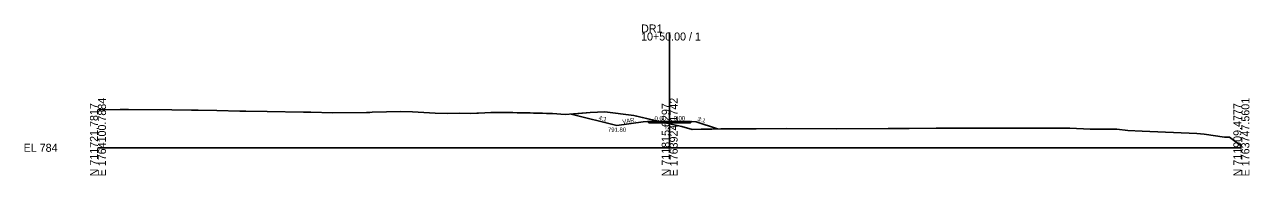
# Model space of a CAD drawing. Extents: x -26 to 403, y -10 to 2023.
# Drawn here: x -25.7 to 402.8, y 990.3 to 1043.1 of the extents above; entities that cross this region are included whole.
import ezdxf

# ---------------------------------------------------------------- set-up
doc = ezdxf.new("R2010")
doc.units = 0
for name, color, linetype in [('Exist Cross Section Cell', 7, 'Continuous'), ('Exist XS Center Line Elevation Label', 7, 'Continuous'), ('Exist XS Ground Line', 7, 'Continuous'), ('Prop CMT Pvmt Surface', 7, 'Continuous'), ('Prop CMT Slope Grass', 7, 'Continuous'), ('Prop CMT Subgrade Earthwork', 7, 'Continuous'), ('Prop XS Earthwork Shape', 7, 'Continuous'), ('Prop XS Side Slope Text', 7, 'Continuous')]:
    doc.layers.add(name, color=color, linetype=linetype)

msp = doc.modelspace()

# ---------------------------------------------------------------- linework, layer by layer
at = {"layer": 'Exist Cross Section Cell'}
for p, q in [((200, 1000), (200, 1040.33)), ((0, 1000), (200, 1000)), ((200, 1000), (400, 1000))]:
    msp.add_line(p, q, dxfattribs=at)
at = {"layer": 'Exist XS Ground Line'}
msp.add_lwpolyline([(0, 1013.23), (7.79, 1013.44), (10.66, 1013.44), (25.89, 1013.29), (32.72, 1013.19), (35.04, 1013.13), (41.56, 1013.02), (49.63, 1012.85), (50.72, 1012.83), (51.02, 1012.8), (51.76, 1012.77), (59.14, 1012.67), (71.87, 1012.47), (74.49, 1012.43), (82.06, 1012.26), (93.89, 1012.39), (95.12, 1012.38), (95.94, 1012.41), (105.9, 1012.74), (110.01, 1012.62), (117.91, 1012.17), (122.14, 1012.01), (126.56, 1012.06), (130.5, 1011.94), (132.54, 1012.13), (133.07, 1012.15), (135.37, 1012.23), (137.39, 1012.33), (138.2, 1012.37), (139.12, 1012.36), (141.03, 1012.34), (142.72, 1012.34), (143.86, 1012.34), (145.16, 1012.3), (146.69, 1012.27), (148.04, 1012.24), (149.52, 1012.23), (151.2, 1012.18), (152.35, 1012.16), (153.37, 1012.14), (155.47, 1012.09), (156.9, 1012), (158.97, 1011.94), (163.41, 1011.63), (172.23, 1012.34), (177.29, 1012.58), (187.46, 1011.25), (200, 1008.41), (204.22, 1007.45), (207.83, 1006.38), (211.02, 1006.49), (214.77, 1006.56), (217.85, 1006.6), (219.41, 1006.59), (221.85, 1006.59), (224.18, 1006.6), (230.21, 1006.68), (241, 1006.72), (258.52, 1006.65), (276.42, 1006.78), (283.8, 1006.8), (293.23, 1006.83), (322.06, 1006.9), (323.31, 1006.9), (328.03, 1006.91), (328.64, 1006.91), (336.97, 1006.9), (339.98, 1006.9), (347.14, 1006.54), (356.43, 1006.55), (360.28, 1006.05), (365.29, 1005.78), (384.37, 1005.04), (386.95, 1004.76), (394.15, 1003.75), (395.87, 1003.68), (398.22, 1001.98), (400, 1000.54)], dxfattribs=at)
at = {"layer": 'Prop CMT Pvmt Surface'}
for p, q in [((200, 1009.25), (192.73, 1009.25)), ((207.27, 1009.25), (200, 1009.25))]:
    msp.add_line(p, q, dxfattribs=at)
at = {"layer": 'Prop CMT Slope Grass'}
for p, q in [((181.52, 1007.8), (165.51, 1011.8)), ((181.52, 1007.8), (190.73, 1009.09)), ((209.27, 1009.09), (216.77, 1006.58))]:
    msp.add_line(p, q, dxfattribs=at)
for points in [[(192.73, 1009.25), (190.73, 1009.09)], [(207.27, 1009.25), (209.27, 1009.09)]]:
    msp.add_lwpolyline(points, dxfattribs=at)
at = {"layer": 'Prop CMT Subgrade Earthwork'}
for p, q in [((192.73, 1008.75), (192.27, 1009.21)), ((200, 1008.75), (192.73, 1008.75)), ((207.27, 1008.75), (200, 1008.75)), ((207.27, 1008.75), (207.73, 1009.21))]:
    msp.add_line(p, q, dxfattribs=at)
at = {"layer": 'Prop XS Earthwork Shape'}
for points in [[(181.52, 1007.8), (190.73, 1009.09), (192.27, 1009.21), (192.73, 1009.25), (196.29, 1009.25), (187.46, 1011.25), (177.29, 1012.58), (172.23, 1012.34), (165.51, 1011.8)], [(198.5, 1008.75), (192.73, 1008.75), (192.27, 1009.21), (192.73, 1009.25), (196.29, 1009.25)], [(207.27, 1008.75), (207.73, 1009.21), (209.27, 1009.09), (216.77, 1006.58), (214.77, 1006.56), (211.02, 1006.49), (207.83, 1006.38), (204.22, 1007.45), (200, 1008.41), (198.5, 1008.75), (200, 1008.75)]]:
    msp.add_lwpolyline(points, close=True, dxfattribs=at)

# ---------------------------------------------------------------- texts
at = {"layer": 'Exist Cross Section Cell'}
for s, p in [('DR1', (190, 1040.33)), ('10+50.00 / 1', (190, 1037.53)), ('EL 784', (-26, 998.6))]:
    msp.add_text(s, height=2.8, dxfattribs=at).set_placement(p)
for s, p in [('E 1764100.7884', (2.8, 990)), ('E 1763924.1742', (202.8, 990)), ('E 1763747.5601', (402.8, 990)), ('N 711721.7817', (0, 990)), ('N 711815.6297', (200, 990)), ('N 711909.4777', (400, 990))]:
    msp.add_text(s, height=2.8, rotation=90, dxfattribs=at).set_placement(p)
at = {"layer": 'Exist XS Center Line Elevation Label'}
for s, height, p in [('791.80', 1.5, (178.42, 1005.59)), ('792.41', 1, (198.1, 1006.41))]:
    msp.add_text(s, height=height, dxfattribs=at).set_placement(p)
at = {"layer": 'Prop XS Side Slope Text'}
for s, rotation, p in [('4:1', 345.9638, (175.02, 1009.86)), ('VAR.', 9.4822, (183.57, 1008.36)), ('3:1', 345.9638, (209.59, 1009.46))]:
    msp.add_text(s, height=1.5, rotation=rotation, dxfattribs=at).set_placement(p)
for p in [(194.71, 1009.54), (201.38, 1009.59)]:
    msp.add_text('0.00', height=1.5, dxfattribs=at).set_placement(p)

doc.saveas('drawing.dxf')
